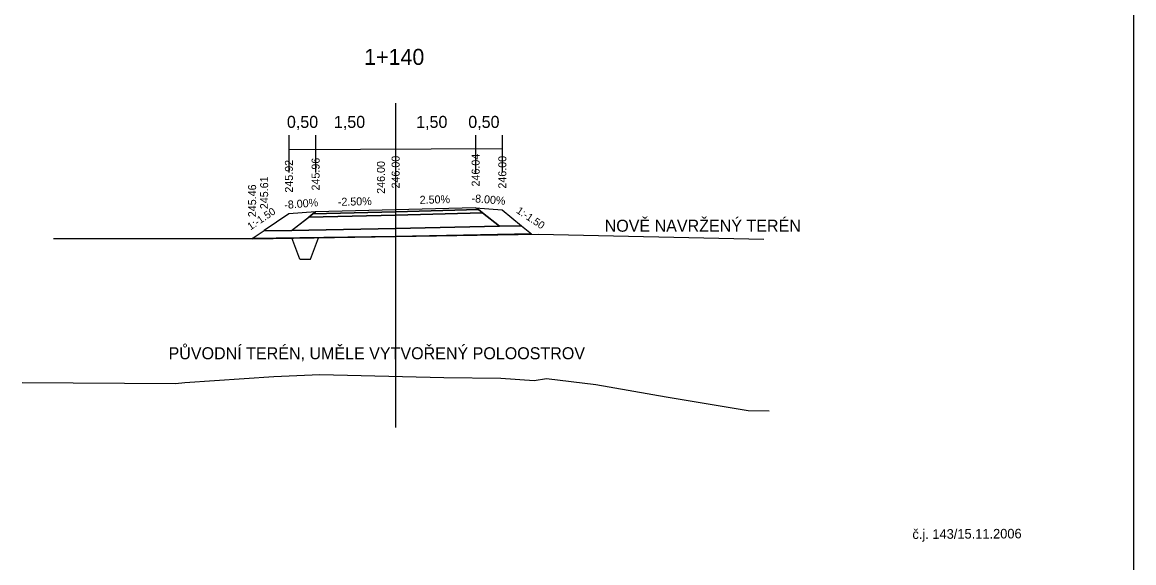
# Model space of a CAD drawing. Extents: x -552501 to -552394, y -1029983 to -1029892.
# Drawn here: x -552436.59 to -552415.76, y -1029971.42 to -1029961.29 of the extents above; entities that cross this region are included whole.
import ezdxf

# ---------------------------------------------------------------- set-up
doc = ezdxf.new("R2010")
doc.units = 0
for name, color, linetype in [('1', 7, 'Continuous'), ('16', 7, 'Continuous'), ('60', 7, 'Continuous'), ('9', 7, 'Continuous'), ('Implicitní', 7, 'Continuous'), ('rámeček', 7, 'Continuous')]:
    doc.layers.add(name, color=color, linetype=linetype)

msp = doc.modelspace()

# ---------------------------------------------------------------- linework, layer by layer
for p, q in [((-552431.39, -1029965.738), (-552431.54, -1029965.338)), ((-552431.19, -1029965.738), (-552431.04, -1029965.338)), ((-552432.273, -1029965.355), (-552436.009, -1029965.355)), ((-552431.39, -1029965.738), (-552431.19, -1029965.738))]:
    msp.add_line(p, q)
for points in [[(-552431.094, -1029964.848), (-552431.594, -1029964.888), (-552432.059, -1029965.198), (-552431.545, -1029965.198)], [(-552431.545, -1029965.198), (-552431.223, -1029964.948), (-552429.595, -1029964.91), (-552427.966, -1029964.867), (-552427.644, -1029965.117), (-552429.595, -1029965.16)], [(-552429.595, -1029964.85), (-552431.145, -1029964.888), (-552431.223, -1029964.948), (-552429.595, -1029964.91), (-552427.966, -1029964.867), (-552428.043, -1029964.807), (-552429.595, -1029964.85), (-552428.043, -1029964.807), (-552428.094, -1029964.773), (-552429.594, -1029964.81), (-552431.094, -1029964.848), (-552431.145, -1029964.888)], [(-552431.223, -1029964.948), (-552431.145, -1029964.888), (-552429.595, -1029964.85), (-552428.043, -1029964.807), (-552427.966, -1029964.867), (-552429.595, -1029964.91)], [(-552428.094, -1029964.773), (-552427.594, -1029964.813), (-552427.233, -1029965.111), (-552427.644, -1029965.117), (-552427.966, -1029964.867), (-552428.043, -1029964.807)], [(-552432.284, -1029965.348), (-552432.059, -1029965.198), (-552431.545, -1029965.198), (-552429.595, -1029965.16), (-552427.644, -1029965.117), (-552427.233, -1029965.111), (-552427.048, -1029965.261), (-552429.595, -1029965.31)]]:
    msp.add_lwpolyline(points, close=True)
for points in [[(-552432.273, -1029965.355), (-552426.916, -1029965.266), (-552422.69, -1029965.362)], [(-552436.594, -1029968.046), (-552433.723, -1029968.066), (-552433.543, -1029968.048), (-552431.88, -1029967.934), (-552431.014, -1029967.899), (-552428.687, -1029967.951), (-552427.62, -1029967.967), (-552426.995, -1029968.008), (-552426.763, -1029967.971), (-552425.842, -1029968.083), (-552424.521, -1029968.318), (-552422.986, -1029968.573), (-552422.594, -1029968.579)]]:
    msp.add_lwpolyline(points)
at = {"layer": '60'}
msp.add_line((-552429.594, -1029962.811), (-552429.594, -1029968.893), dxfattribs=at)
at = {"layer": '9'}
for p, q in [((-552431.595, -1029963.41), (-552431.595, -1029964.108)), ((-552431.095, -1029963.41), (-552431.095, -1029964.108)), ((-552429.595, -1029963.41), (-552429.595, -1029964.91)), ((-552428.095, -1029963.41), (-552428.095, -1029964.108)), ((-552427.595, -1029963.41), (-552427.595, -1029964.108))]:
    msp.add_line(p, q, dxfattribs=at)
at = {"layer": 'Implicitní'}
msp.add_line((-552431.585, -1029963.678), (-552427.595, -1029963.66), dxfattribs=at)
at = {"layer": 'rámeček'}
msp.add_line((-552415.755, -1029982.45), (-552415.755, -1029952.718), dxfattribs=at)

# ---------------------------------------------------------------- texts
for rotation, p in [(33.6902, (-552432.315, -1029965.198)), (326.3098, (-552427.343, -1029964.857))]:
    msp.add_text('1:-1.50', height=0.14, rotation=rotation).set_placement(p)
at = {"layer": '1'}
msp.add_text('1+140', height=0.3, dxfattribs=at).set_placement((-552430.183, -1029962.094))
at = {"layer": '16'}
for s, p in [('0,50', (-552431.632, -1029963.275)), ('1,50', (-552430.751, -1029963.275)), ('1,50', (-552429.209, -1029963.275)), ('0,50', (-552428.232, -1029963.275)), ('NOVĚ NAVRŽENÝ TERÉN', (-552425.675, -1029965.221)), ('PŮVODNÍ TERÉN, UMĚLE VYTVOŘENÝ POLOOSTROV', (-552433.851, -1029967.611))]:
    msp.add_text(s, height=0.225, dxfattribs=at).set_placement(p)
for s, rotation, p in [('245.92', 90, (-552431.519, -1029964.488)), ('245.96', 90, (-552431.019, -1029964.448)), ('246.00', 90, (-552429.519, -1029964.41)), ('246.04', 90, (-552428.019, -1029964.373)), ('246.00', 90, (-552427.519, -1029964.413)), ('246.00', 90, (-552429.794, -1029964.51)), ('245.61', 90, (-552431.984, -1029964.798)), ('245.46', 90, (-552432.209, -1029964.948)), ('-8.00%', 4.5739, (-552431.675, -1029964.794)), ('-2.50%', 1.4321, (-552430.676, -1029964.737)), ('2.50%', 1.4321, (-552429.141, -1029964.699)), ('-8.00%', 355.4261, (-552428.175, -1029964.666))]:
    msp.add_text(s, height=0.15, rotation=rotation, dxfattribs=at).set_placement(p)
at = {"layer": 'rámeček'}
msp.add_text('č.j. 143/15.11.2006', height=0.18, rotation=0.3084, dxfattribs=at).set_placement((-552419.905, -1029970.979))

doc.saveas('drawing.dxf')
